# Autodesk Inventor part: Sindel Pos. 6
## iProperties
Created: 2009-11
Part Number: Sindel Pos. 6
Document SubType Name: Modeling
Designer: user
Author: user
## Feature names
1. Drehung1 [Revolution]
2. Bohrung1 [Hole]
3. Fase1 [Chamfer]
4. Fase2 [Chamfer]
